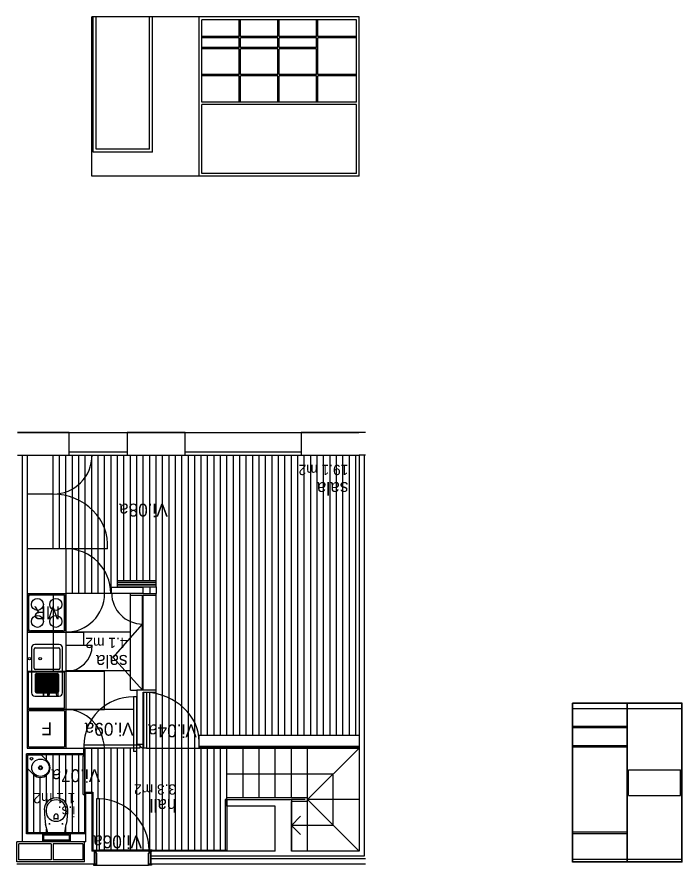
# Model space of a CAD drawing. Extents: x 1308.7 to 1320.6, y -286 to -262.2.
# Drawn here: x 1308.74 to 1319.07, y -275.33 to -262.16 of the extents above; entities that cross this region are included whole.
import ezdxf

# ---------------------------------------------------------------- set-up
doc = ezdxf.new("R2010")
doc.units = 0
for name, color, linetype in [('Level 1', 7, 'Continuous'), ('Level 10', 7, 'Continuous'), ('Level 11', 7, 'Continuous'), ('Level 12', 7, 'Continuous'), ('Level 13', 7, 'Continuous'), ('Level 2', 7, 'Continuous'), ('Level 21', 7, 'Continuous'), ('Level 3', 7, 'Continuous'), ('Level 31', 7, 'Continuous'), ('Level 36', 7, 'Continuous'), ('Level 4', 7, 'Continuous'), ('Level 60', 7, 'Continuous')]:
    doc.layers.add(name, color=color, linetype=linetype)

msp = doc.modelspace()

# ---------------------------------------------------------------- linework, layer by layer
at = {"layer": 'Level 1'}
for p, q in [((1309.903, -264.629), (1309.903, -262.159)), ((1314.053, -262.159), (1309.903, -262.159)), ((1314.053, -264.629), (1314.053, -262.159)), ((1314.053, -264.629), (1309.903, -264.629)), ((1309.553, -268.612), (1308.753, -268.612)), ((1309.553, -268.962), (1309.553, -268.612)), ((1311.353, -268.612), (1310.453, -268.612)), ((1310.453, -268.612), (1310.453, -268.962)), ((1311.353, -268.962), (1311.353, -268.612)), ((1314.153, -268.612), (1313.153, -268.612)), ((1313.153, -268.612), (1313.153, -268.962)), ((1308.753, -268.962), (1308.853, -268.962)), ((1308.753, -268.962), (1309.553, -268.962)), ((1308.823, -268.962), (1308.823, -274.967)), ((1308.903, -268.962), (1308.903, -273.512)), ((1308.903, -268.962), (1308.903, -270.712)), ((1310.453, -268.962), (1311.353, -268.962)), ((1313.153, -268.962), (1314.053, -268.962)), ((1314.153, -268.962), (1314.053, -268.962)), ((1314.053, -268.962), (1314.053, -275.112)), ((1314.133, -268.962), (1314.133, -275.192)), ((1308.903, -270.812), (1308.903, -273.512)), ((1310.203, -271.012), (1310.703, -271.012)), ((1310.203, -271.012), (1310.203, -271.112)), ((1310.703, -271.112), (1310.203, -271.112)), ((1310.503, -271.144), (1310.503, -271.112)), ((1310.703, -271.112), (1310.703, -271.012)), ((1310.703, -271.112), (1310.903, -271.112)), ((1310.903, -271.144), (1310.903, -271.112)), ((1310.903, -271.144), (1310.503, -271.144)), ((1310.903, -272.612), (1310.603, -272.612)), ((1310.603, -272.612), (1310.603, -273.452)), ((1310.703, -272.612), (1310.603, -272.612)), ((1310.603, -272.612), (1310.603, -273.452)), ((1310.703, -273.452), (1310.703, -272.644)), ((1310.703, -272.644), (1310.903, -272.644)), ((1310.903, -272.644), (1310.903, -272.612)), ((1317.367, -275.285), (1317.367, -272.815)), ((1319.067, -272.815), (1317.367, -272.815)), ((1319.067, -275.285), (1319.067, -272.815)), ((1310.603, -273.452), (1310.703, -273.452)), ((1310.603, -273.452), (1310.703, -273.452)), ((1309.778, -273.602), (1308.893, -273.602)), ((1308.893, -274.842), (1308.893, -273.602)), ((1308.903, -273.512), (1309.778, -273.512)), ((1308.903, -273.512), (1309.778, -273.512)), ((1309.778, -273.617), (1308.908, -273.617)), ((1308.908, -273.617), (1308.908, -274.827)), ((1309.778, -273.512), (1309.778, -273.617)), ((1309.798, -274.212), (1309.903, -274.212)), ((1309.798, -274.827), (1309.798, -274.212)), ((1309.813, -274.967), (1309.813, -274.212)), ((1309.903, -274.212), (1309.903, -275.112)), ((1312.003, -274.412), (1312.003, -274.312)), ((1312.003, -274.312), (1313.003, -274.312)), ((1312.753, -274.412), (1312.003, -274.412)), ((1312.753, -275.112), (1312.753, -274.412)), ((1313.003, -274.312), (1313.003, -275.112)), ((1309.813, -274.842), (1308.893, -274.842)), ((1309.798, -274.827), (1308.908, -274.827)), ((1309.813, -274.967), (1308.743, -274.967)), ((1308.743, -275.277), (1308.743, -274.967)), ((1308.773, -275.247), (1308.773, -274.997)), ((1309.273, -274.997), (1308.773, -274.997)), ((1309.273, -274.997), (1309.273, -275.247)), ((1309.303, -274.997), (1309.303, -275.247)), ((1309.763, -274.997), (1309.303, -274.997)), ((1309.763, -274.997), (1309.763, -275.247)), ((1309.793, -275.277), (1309.793, -274.967)), ((1309.943, -275.112), (1309.903, -275.112)), ((1309.943, -275.112), (1309.943, -275.312)), ((1310.823, -275.112), (1310.823, -275.312)), ((1312.753, -275.112), (1310.823, -275.112)), ((1314.133, -275.192), (1310.823, -275.192)), ((1314.053, -275.112), (1313.003, -275.112)), ((1309.793, -275.277), (1308.743, -275.277)), ((1309.943, -275.312), (1308.743, -275.312)), ((1309.273, -275.247), (1308.773, -275.247)), ((1309.763, -275.247), (1309.303, -275.247)), ((1314.153, -275.232), (1310.823, -275.232)), ((1314.153, -275.312), (1310.823, -275.312)), ((1319.067, -275.285), (1317.367, -275.285))]:
    msp.add_line(p, q, dxfattribs=at)
at = {"layer": 'Level 10'}
for p, q in [((1309.403, -270.415), (1309.403, -268.962)), ((1309.503, -270.415), (1309.503, -268.962)), ((1309.603, -271.112), (1309.603, -268.962)), ((1309.703, -271.112), (1309.703, -268.962)), ((1309.803, -271.112), (1309.803, -268.962)), ((1309.903, -271.112), (1309.903, -268.962)), ((1310.003, -271.112), (1310.003, -268.962)), ((1310.103, -271.112), (1310.103, -268.962)), ((1310.203, -271.007), (1310.203, -268.962)), ((1310.303, -270.907), (1310.303, -268.962)), ((1310.403, -270.907), (1310.403, -268.962)), ((1310.503, -270.907), (1310.503, -268.962)), ((1310.603, -270.907), (1310.603, -268.962)), ((1310.703, -270.907), (1310.703, -268.962)), ((1310.803, -270.907), (1310.803, -268.962)), ((1310.903, -270.907), (1310.903, -268.962)), ((1311.003, -275.097), (1311.003, -268.962)), ((1311.103, -275.097), (1311.103, -268.962)), ((1311.203, -275.097), (1311.203, -268.962)), ((1311.303, -275.097), (1311.303, -268.962)), ((1311.403, -275.097), (1311.403, -268.962)), ((1311.503, -275.097), (1311.503, -268.962)), ((1311.603, -273.312), (1311.603, -268.962)), ((1311.703, -273.312), (1311.703, -268.962)), ((1311.803, -273.312), (1311.803, -268.962)), ((1311.903, -273.312), (1311.903, -268.962)), ((1312.003, -273.312), (1312.003, -268.962)), ((1312.103, -273.312), (1312.103, -268.962)), ((1312.203, -273.312), (1312.203, -268.962)), ((1312.303, -273.312), (1312.303, -268.962)), ((1312.403, -273.312), (1312.403, -268.962)), ((1312.503, -273.312), (1312.503, -268.962)), ((1312.603, -273.312), (1312.603, -268.962)), ((1312.703, -273.312), (1312.703, -268.962)), ((1312.803, -273.312), (1312.803, -268.962)), ((1312.903, -273.312), (1312.903, -268.962)), ((1313.003, -273.312), (1313.003, -268.962)), ((1313.103, -273.312), (1313.103, -268.962)), ((1313.203, -273.312), (1313.203, -268.962)), ((1313.303, -273.312), (1313.303, -268.962)), ((1313.403, -273.312), (1313.403, -268.962)), ((1313.503, -273.312), (1313.503, -268.962)), ((1313.603, -273.312), (1313.603, -268.962)), ((1313.703, -273.312), (1313.703, -268.962)), ((1313.803, -273.312), (1313.803, -268.962)), ((1313.903, -273.312), (1313.903, -268.962)), ((1314.003, -273.312), (1314.003, -268.962)), ((1310.203, -271.112), (1309.506, -271.112)), ((1310.803, -271.007), (1310.803, -271.112)), ((1310.903, -271.007), (1310.903, -271.112)), ((1310.503, -271.712), (1309.503, -271.712)), ((1310.503, -272.312), (1309.503, -272.312)), ((1310.803, -275.097), (1310.803, -272.644)), ((1310.903, -275.097), (1310.903, -272.644)), ((1310.553, -272.912), (1309.503, -272.912)), ((1310.603, -275.112), (1310.603, -273.452)), ((1310.703, -275.112), (1310.703, -273.452)), ((1309.203, -273.699), (1309.203, -273.617)), ((1309.303, -274.293), (1309.303, -273.617)), ((1309.403, -274.294), (1309.403, -273.617)), ((1309.503, -274.37), (1309.503, -273.617)), ((1309.603, -274.827), (1309.603, -273.617)), ((1309.703, -274.827), (1309.703, -273.617)), ((1309.803, -274.197), (1309.803, -273.512)), ((1309.903, -274.197), (1309.903, -273.512)), ((1310.003, -274.297), (1310.003, -273.512)), ((1310.103, -275.112), (1310.103, -273.512)), ((1310.203, -275.112), (1310.203, -273.512)), ((1310.303, -275.112), (1310.303, -273.512)), ((1310.403, -275.112), (1310.403, -273.512)), ((1310.503, -275.112), (1310.503, -273.512)), ((1311.603, -275.097), (1311.603, -273.512)), ((1311.703, -275.097), (1311.703, -273.512)), ((1311.803, -275.097), (1311.803, -273.512)), ((1311.903, -275.097), (1311.903, -273.512)), ((1309.003, -274.827), (1309.003, -273.925)), ((1309.103, -274.827), (1309.103, -273.967)), ((1309.203, -274.358), (1309.203, -273.935)), ((1309.203, -274.827), (1309.203, -274.77)), ((1309.503, -274.827), (1309.503, -274.727)), ((1310.793, -275.112), (1309.973, -275.112))]:
    msp.add_line(p, q, dxfattribs=at)
at = {"layer": 'Level 11'}
for p, q in [((1309.453, -271.132), (1308.953, -271.132)), ((1308.923, -271.662), (1308.923, -271.162)), ((1309.483, -271.662), (1309.483, -271.162)), ((1309.453, -271.692), (1308.953, -271.692)), ((1309.008, -272.273), (1309.008, -271.973)), ((1309.028, -271.953), (1309.388, -271.953)), ((1309.408, -271.973), (1309.408, -272.273)), ((1309.388, -272.293), (1309.028, -272.293)), ((1309.028, -272.371), (1309.028, -272.633)), ((1309.048, -272.351), (1309.368, -272.351)), ((1309.048, -272.351), (1309.048, -272.653)), ((1309.068, -272.351), (1309.068, -272.653)), ((1309.088, -272.351), (1309.088, -272.653)), ((1309.108, -272.351), (1309.108, -272.653)), ((1309.128, -272.351), (1309.128, -272.653)), ((1309.148, -272.351), (1309.148, -272.653)), ((1309.168, -272.351), (1309.168, -272.653)), ((1309.188, -272.351), (1309.188, -272.653)), ((1309.208, -272.351), (1309.208, -272.653)), ((1309.228, -272.351), (1309.228, -272.653)), ((1309.248, -272.351), (1309.248, -272.653)), ((1309.268, -272.351), (1309.268, -272.653)), ((1309.288, -272.351), (1309.288, -272.653)), ((1309.308, -272.351), (1309.308, -272.653)), ((1309.328, -272.351), (1309.328, -272.653)), ((1309.348, -272.351), (1309.348, -272.653)), ((1309.368, -272.351), (1309.368, -272.653)), ((1309.388, -272.371), (1309.388, -272.633)), ((1309.048, -272.653), (1309.368, -272.653)), ((1309.483, -272.932), (1308.923, -272.932)), ((1308.923, -273.492), (1308.923, -272.932)), ((1309.483, -272.932), (1309.483, -273.492)), ((1308.923, -273.492), (1309.483, -273.492)), ((1308.908, -273.617), (1309.12, -273.617)), ((1308.908, -273.829), (1308.908, -273.617)), ((1309.214, -273.711), (1309.12, -273.617)), ((1309.002, -273.923), (1308.908, -273.829)), ((1309.168, -274.468), (1309.168, -274.464)), ((1309.198, -274.464), (1309.198, -274.5)), ((1309.503, -274.464), (1309.503, -274.5)), ((1309.533, -274.468), (1309.533, -274.464)), ((1309.24, -274.688), (1309.26, -274.688)), ((1309.25, -274.698), (1309.25, -274.678)), ((1309.32, -274.622), (1309.32, -274.565)), ((1309.32, -274.604), (1309.38, -274.604)), ((1309.38, -274.622), (1309.38, -274.565)), ((1309.44, -274.688), (1309.46, -274.688)), ((1309.45, -274.698), (1309.45, -274.678)), ((1309.221, -274.827), (1309.187, -274.695)), ((1309.485, -274.827), (1309.509, -274.695)), ((1309.138, -274.847), (1309.138, -274.957)), ((1309.568, -274.847), (1309.138, -274.847)), ((1309.553, -274.862), (1309.153, -274.862)), ((1309.153, -274.862), (1309.153, -274.942)), ((1309.553, -274.942), (1309.153, -274.942)), ((1309.221, -274.827), (1309.485, -274.827)), ((1309.553, -274.862), (1309.553, -274.942)), ((1309.568, -274.847), (1309.568, -274.957)), ((1309.568, -274.957), (1309.138, -274.957))]:
    msp.add_line(p, q, dxfattribs=at)
for points in [[(1309.399, -271.902), (1309.02, -271.902)], [(1308.97, -271.952), (1308.97, -272.653)], [(1309.449, -272.653), (1309.449, -271.952)], [(1309.02, -272.703), (1309.399, -272.703)]]:
    msp.add_lwpolyline(points, dxfattribs=at)
for centre, radius in [((1309.06, -271.28), 0.0936), ((1309.346, -271.28), 0.0936), ((1309.06, -271.544), 0.0936), ((1309.346, -271.544), 0.0936), ((1308.938, -272.123), 0.0199), ((1309.104, -272.123), 0.0199), ((1308.968, -273.677), 0.02), ((1309.108, -273.817), 0.135), ((1309.108, -273.817), 0.03), ((1309.108, -273.817), 0.02)]:
    msp.add_circle(centre, radius, dxfattribs=at)
for centre, radius, start, end in [((1308.953, -271.162), 0.03, 90, 179.9998), ((1309.453, -271.162), 0.03, 360, 89.9999), ((1308.953, -271.662), 0.03, 179.9998, 270.0001), ((1309.453, -271.662), 0.03, 269.9999, 359.9999), ((1309.02, -271.952), 0.05, 90, 180), ((1309.399, -271.952), 0.05, 0, 90), ((1309.028, -271.973), 0.02, 90, 180), ((1309.388, -271.973), 0.02, 0, 90), ((1309.028, -272.273), 0.02, 180, 270), ((1309.388, -272.273), 0.02, 270, 0), ((1309.048, -272.371), 0.02, 90, 180), ((1309.368, -272.371), 0.02, 0, 90), ((1309.02, -272.653), 0.05, 180, 270), ((1309.048, -272.633), 0.02, 180, 270), ((1309.368, -272.633), 0.02, 270, 0), ((1309.399, -272.653), 0.05, 270, 0), ((1309.108, -273.817), 0.15, 225.0002, 45), ((1309.35, -274.565), 0.03, 359.9987, 180.0005)]:
    msp.add_arc(centre, radius, start, end, dxfattribs=at)
for centre, major_axis, ratio, start_param, end_param in [((1309.35, -274.464), (0.183, 0), 0.972581, 0.000002, 3.141589), ((1309.35, -274.464), (0.153, 0), 0.967187, 0.000002, 3.141589), ((1310.568, -274.468), (0, 1.4), 0.999692, 1.570794, 1.733712), ((1309.35, -274.5), (0.153, 0), 0.967187, 3.141595, 6.283182), ((1307.755, -274.468), (1.778, 0), 0.787256, 6.120268, 6.283186)]:
    msp.add_ellipse(centre, major_axis=major_axis, ratio=ratio, start_param=start_param, end_param=end_param, dxfattribs=at)
at = {"layer": 'Level 12'}
for p, q in [((1311.571, -264.629), (1311.571, -262.159)), ((1314.013, -262.204), (1311.611, -262.204)), ((1311.611, -263.48), (1311.611, -262.204)), ((1312.193, -262.464), (1312.193, -262.204)), ((1312.213, -262.464), (1312.213, -262.204)), ((1312.793, -262.464), (1312.793, -262.204)), ((1312.813, -262.464), (1312.813, -262.204)), ((1313.393, -262.464), (1313.393, -262.204)), ((1313.413, -262.464), (1313.413, -262.204)), ((1314.013, -263.48), (1314.013, -262.204)), ((1312.193, -262.464), (1311.611, -262.464)), ((1312.193, -262.484), (1311.611, -262.484)), ((1312.193, -262.634), (1312.193, -262.484)), ((1312.793, -262.464), (1312.213, -262.464)), ((1312.793, -262.484), (1312.213, -262.484)), ((1312.213, -262.634), (1312.213, -262.484)), ((1312.793, -262.634), (1312.793, -262.484)), ((1313.393, -262.464), (1312.813, -262.464)), ((1312.813, -262.634), (1312.813, -262.484)), ((1313.393, -262.484), (1312.813, -262.484)), ((1313.393, -262.634), (1313.393, -262.484)), ((1314.013, -262.464), (1313.413, -262.464)), ((1314.013, -262.484), (1313.413, -262.484)), ((1313.413, -263.055), (1313.413, -262.484)), ((1312.193, -262.634), (1311.611, -262.634)), ((1312.193, -262.654), (1311.611, -262.654)), ((1312.193, -263.055), (1312.193, -262.654)), ((1312.793, -262.634), (1312.213, -262.634)), ((1312.793, -262.654), (1312.213, -262.654)), ((1312.213, -263.055), (1312.213, -262.654)), ((1312.793, -263.055), (1312.793, -262.654)), ((1313.393, -262.634), (1312.813, -262.634)), ((1313.393, -262.654), (1312.813, -262.654)), ((1312.813, -263.055), (1312.813, -262.654)), ((1313.393, -263.055), (1313.393, -262.654)), ((1312.193, -263.055), (1311.611, -263.055)), ((1312.193, -263.075), (1311.611, -263.075)), ((1312.193, -263.48), (1312.193, -263.075)), ((1312.793, -263.055), (1312.213, -263.055)), ((1312.793, -263.075), (1312.213, -263.075)), ((1312.213, -263.48), (1312.213, -263.075)), ((1312.793, -263.48), (1312.793, -263.075)), ((1313.393, -263.055), (1312.813, -263.055)), ((1313.393, -263.075), (1312.813, -263.075)), ((1312.813, -263.48), (1312.813, -263.075)), ((1313.393, -263.48), (1313.393, -263.075)), ((1314.013, -263.055), (1313.413, -263.055)), ((1314.013, -263.075), (1313.413, -263.075)), ((1313.413, -263.48), (1313.413, -263.075)), ((1314.013, -263.48), (1311.611, -263.48)), ((1314.013, -263.52), (1311.611, -263.52)), ((1311.611, -264.589), (1311.611, -263.52)), ((1314.013, -264.589), (1314.013, -263.52)), ((1314.053, -264.629), (1311.571, -264.629)), ((1314.013, -264.589), (1311.611, -264.589))]:
    msp.add_line(p, q, dxfattribs=at)
at = {"layer": 'Level 13'}
for p, q in [((1309.928, -264.259), (1309.928, -262.159)), ((1309.973, -264.214), (1309.973, -262.159)), ((1310.8, -264.214), (1310.8, -262.159)), ((1310.845, -264.259), (1310.845, -262.159)), ((1310.845, -264.259), (1309.928, -264.259)), ((1310.8, -264.214), (1309.973, -264.214)), ((1309.303, -270.415), (1309.303, -268.962)), ((1309.503, -270.415), (1308.903, -270.415)), ((1309.503, -270.415), (1309.503, -273.512)), ((1310.303, -270.907), (1310.903, -270.907)), ((1310.303, -271.007), (1310.303, -270.907)), ((1310.303, -270.937), (1310.903, -270.937)), ((1310.303, -270.942), (1310.903, -270.942)), ((1310.303, -270.972), (1310.903, -270.972)), ((1310.303, -270.977), (1310.903, -270.977)), ((1310.903, -271.007), (1310.903, -270.907)), ((1310.903, -271.007), (1310.903, -270.907)), ((1310.303, -271.007), (1310.903, -271.007)), ((1310.708, -272.647), (1310.708, -273.512)), ((1310.753, -272.647), (1310.708, -272.647)), ((1310.753, -272.647), (1310.753, -273.512)), ((1310.598, -272.717), (1310.553, -272.717)), ((1310.553, -272.717), (1310.553, -273.562)), ((1310.598, -272.717), (1310.598, -273.562)), ((1319.062, -272.82), (1317.367, -272.82)), ((1317.372, -275.28), (1317.372, -272.815)), ((1318.216, -275.28), (1318.216, -272.82)), ((1318.218, -275.28), (1318.218, -272.82)), ((1319.062, -275.28), (1319.062, -272.82)), ((1309.503, -272.912), (1308.903, -272.912)), ((1311.571, -273.512), (1311.571, -273.312)), ((1311.571, -273.312), (1314.049, -273.312)), ((1309.768, -273.632), (1309.798, -273.632)), ((1309.768, -274.232), (1309.768, -273.632)), ((1309.778, -273.632), (1309.798, -273.632)), ((1309.798, -274.232), (1309.798, -273.632)), ((1310.598, -273.562), (1310.553, -273.562)), ((1310.753, -273.512), (1310.708, -273.512)), ((1311.571, -273.512), (1314.053, -273.512)), ((1311.571, -273.512), (1314.053, -273.512)), ((1311.571, -273.512), (1314.053, -273.512)), ((1311.999, -273.512), (1314.053, -273.512)), ((1318.238, -273.85), (1319.042, -273.85)), ((1318.238, -274.25), (1318.238, -273.85)), ((1319.042, -274.25), (1319.042, -273.85)), ((1309.768, -274.232), (1309.798, -274.232)), ((1309.798, -274.197), (1309.918, -274.197)), ((1309.918, -274.197), (1309.918, -275.112)), ((1318.238, -274.25), (1319.042, -274.25)), ((1309.978, -274.297), (1309.978, -275.097)), ((1310.022, -274.297), (1309.978, -274.297)), ((1310.022, -275.097), (1310.022, -274.297)), ((1311.973, -274.312), (1311.973, -275.097)), ((1312.003, -274.312), (1311.973, -274.312)), ((1312.003, -274.312), (1312.003, -275.112)), ((1309.923, -275.097), (1309.973, -275.097)), ((1309.923, -275.107), (1309.923, -275.097)), ((1309.928, -275.107), (1309.923, -275.107)), ((1309.928, -275.112), (1309.928, -275.107)), ((1309.973, -275.112), (1309.928, -275.112)), ((1309.953, -275.112), (1309.953, -275.312)), ((1309.973, -275.097), (1309.973, -275.112)), ((1309.973, -275.141), (1309.973, -275.112)), ((1309.983, -275.141), (1309.973, -275.141)), ((1309.978, -275.097), (1310.022, -275.097)), ((1309.983, -275.312), (1309.983, -275.141)), ((1310.783, -275.312), (1310.783, -275.141)), ((1310.783, -275.141), (1310.793, -275.141)), ((1310.843, -275.097), (1310.793, -275.097)), ((1310.793, -275.097), (1310.793, -275.112)), ((1310.793, -275.112), (1310.838, -275.112)), ((1310.793, -275.141), (1310.793, -275.112)), ((1310.793, -275.112), (1310.813, -275.112)), ((1310.813, -275.112), (1310.813, -275.312)), ((1310.838, -275.112), (1310.838, -275.107)), ((1310.838, -275.107), (1310.843, -275.107)), ((1310.843, -275.107), (1310.843, -275.097)), ((1310.843, -275.097), (1312.003, -275.097)), ((1309.938, -275.317), (1309.933, -275.317)), ((1309.933, -275.317), (1309.933, -275.327)), ((1309.933, -275.327), (1309.983, -275.327)), ((1309.983, -275.312), (1309.938, -275.312)), ((1309.938, -275.312), (1309.938, -275.317)), ((1309.953, -275.312), (1309.983, -275.312)), ((1309.983, -275.327), (1309.983, -275.312)), ((1310.813, -275.312), (1310.783, -275.312)), ((1310.783, -275.327), (1310.783, -275.312)), ((1310.783, -275.312), (1310.828, -275.312)), ((1310.833, -275.327), (1310.783, -275.327)), ((1310.828, -275.312), (1310.828, -275.317)), ((1310.828, -275.317), (1310.833, -275.317)), ((1310.833, -275.317), (1310.833, -275.327)), ((1318.216, -275.28), (1317.372, -275.28)), ((1319.062, -275.28), (1318.218, -275.28))]:
    msp.add_line(p, q, dxfattribs=at)
at = {"layer": 'Level 2'}
for p, q in [((1309.553, -268.612), (1310.453, -268.612)), ((1311.353, -268.612), (1313.153, -268.612)), ((1309.553, -268.912), (1310.453, -268.912)), ((1309.553, -268.962), (1310.453, -268.962)), ((1311.353, -268.912), (1313.153, -268.912)), ((1311.353, -268.962), (1313.153, -268.962)), ((1310.503, -272.612), (1310.503, -271.144)), ((1310.903, -272.612), (1310.903, -271.144)), ((1310.503, -272.612), (1310.603, -272.612)), ((1312.003, -274.312), (1312.003, -273.512)), ((1312.253, -274.282), (1312.253, -273.512)), ((1312.503, -274.282), (1312.503, -273.512)), ((1312.753, -274.282), (1312.753, -273.512)), ((1313.003, -274.282), (1313.003, -273.512)), ((1313.253, -274.282), (1313.253, -273.512)), ((1313.253, -274.312), (1314.053, -273.512)), ((1312.003, -273.912), (1313.653, -273.912)), ((1313.653, -274.712), (1313.653, -273.912)), ((1313.253, -274.282), (1312.003, -274.282)), ((1313.253, -274.342), (1313.253, -274.282)), ((1313.219, -274.312), (1313.003, -274.312)), ((1313.003, -275.112), (1313.003, -274.342)), ((1313.253, -274.342), (1313.003, -274.342)), ((1314.053, -274.312), (1313.253, -274.312)), ((1313.253, -274.312), (1314.053, -275.112)), ((1313.253, -275.112), (1313.253, -274.342)), ((1313.144, -274.571), (1313.003, -274.712)), ((1313.144, -274.854), (1313.003, -274.712)), ((1313.653, -274.712), (1313.003, -274.712))]:
    msp.add_line(p, q, dxfattribs=at)
at = {"layer": 'Level 21'}
msp.add_line((1308.753, -268.612), (1314.048, -268.612), dxfattribs=at)
at = {"layer": 'Level 3'}
for p, q in [((1309.303, -271.112), (1309.303, -272.322)), ((1309.303, -271.112), (1309.503, -271.112)), ((1309.503, -272.322), (1308.903, -272.322))]:
    msp.add_line(p, q, dxfattribs=at)
at = {"layer": 'Level 31'}
for p, q in [((1309.798, -273.512), (1309.778, -273.512)), ((1309.798, -273.617), (1309.778, -273.617)), ((1309.798, -273.512), (1309.798, -273.617))]:
    msp.add_line(p, q, dxfattribs=at)
at = {"layer": 'Level 36'}
for p, q in [((1310.693, -272.612), (1310.693, -271.144)), ((1310.703, -272.612), (1310.703, -271.144)), ((1311.571, -273.482), (1314.053, -273.482)), ((1311.571, -273.492), (1314.053, -273.492))]:
    msp.add_line(p, q, dxfattribs=at)
at = {"layer": 'Level 4'}
for p, q in [((1309.303, -269.568), (1308.903, -269.568)), ((1310.148, -270.415), (1309.303, -270.415)), ((1308.903, -271.112), (1309.303, -271.112)), ((1308.923, -271.132), (1309.483, -271.132)), ((1308.923, -271.132), (1308.923, -271.692)), ((1309.483, -271.132), (1309.483, -271.692)), ((1310.237, -272.105), (1310.693, -271.587)), ((1308.903, -271.712), (1309.503, -271.71)), ((1308.923, -271.692), (1309.483, -271.692)), ((1309.503, -271.71), (1309.78, -271.71)), ((1309.78, -271.914), (1309.78, -271.71)), ((1309.503, -271.914), (1309.911, -271.914)), ((1310.693, -272.612), (1310.237, -272.105)), ((1309.483, -272.332), (1308.923, -272.332)), ((1308.923, -272.892), (1308.923, -272.332)), ((1309.483, -272.892), (1309.483, -272.332)), ((1310.103, -272.322), (1309.503, -272.322)), ((1310.103, -272.912), (1310.103, -272.322)), ((1308.923, -272.892), (1309.483, -272.892)), ((1309.503, -272.912), (1310.103, -272.912)), ((1319.062, -272.9), (1317.367, -272.9)), ((1318.218, -273.178), (1317.372, -273.178)), ((1318.218, -273.198), (1317.372, -273.198)), ((1310.648, -273.467), (1309.783, -273.467)), ((1309.783, -273.477), (1309.783, -273.512)), ((1310.648, -273.467), (1310.648, -273.512)), ((1318.218, -273.475), (1317.367, -273.475)), ((1318.218, -273.495), (1317.367, -273.495)), ((1308.903, -273.512), (1309.503, -273.512)), ((1309.503, -273.512), (1310.103, -273.512)), ((1310.648, -273.512), (1309.783, -273.512)), ((1310.753, -273.512), (1311.571, -273.512)), ((1318.216, -274.815), (1317.367, -274.815)), ((1318.216, -274.845), (1317.367, -274.845)), ((1310.793, -275.097), (1310.022, -275.097)), ((1309.983, -275.327), (1310.783, -275.327)), ((1319.067, -275.24), (1317.372, -275.24))]:
    msp.add_line(p, q, dxfattribs=at)
for centre, radius, start, end in [((1309.303, -268.962), 0.606, 270, 0), ((1309.503, -271.112), 0.697, 0, 90), ((1309.503, -271.11), 0.6, 270, 359.7775), ((1310.693, -271.105), 0.48, 180, 270), ((1309.503, -271.914), 0.408, 270, 0), ((1310.537, -273.471), 0.754, 88.8015, 180.4703), ((1310.708, -273.452), 0.06, 179.997, 270.0014)]:
    msp.add_arc(centre, radius, start, end, dxfattribs=at)
for centre, major_axis, ratio, start_param, end_param in [((1309.303, -270.359), (-0.847, 0), 0.932777, 3.069792, 4.712389), ((1310.688, -273.412), (-0.883, 0), 0.869294, 3.141609, 4.638298), ((1309.503, -273.563), (0, 0.651), 0.924693, 4.790593, 6.283185), ((1309.987, -275.097), (-0.806, 0), 0.992512, 3.141593, 4.668897)]:
    msp.add_ellipse(centre, major_axis=major_axis, ratio=ratio, start_param=start_param, end_param=end_param, dxfattribs=at)

# ---------------------------------------------------------------- texts
at = {"layer": 'Level 11'}
for s, p in [('MR', (1309.414, -271.312)), ('ML', (1309.412, -272.512)), ('F', (1309.287, -273.112))]:
    msp.add_text(s, height=0.2, rotation=180, dxfattribs=at).set_placement(p)
at = {"layer": 'Level 60'}
for s, height, p in [('19.1 m2', 0.16, (1313.887, -269.113)), ('sala', 0.2, (1313.887, -269.381)), ('Vi.08a', 0.2, (1311.085, -269.716)), ('4.1 m2', 0.16, (1310.459, -271.798)), ('sala', 0.2, (1310.459, -272.066)), ('Vi.09a', 0.2, (1310.553, -273.119)), ('Vi.04a', 0.2, (1311.535, -273.144)), ('Vi.07a', 0.2, (1310.036, -273.84)), ('3.3 m2', 0.16, (1311.214, -274.074)), ('1.1 m2', 0.16, (1309.65, -274.208)), ('i.s.', 0.16, (1309.65, -274.417)), ('hall', 0.2, (1311.219, -274.303)), ('Vi.06a', 0.2, (1310.683, -274.867))]:
    msp.add_text(s, height=height, rotation=180, dxfattribs=at).set_placement(p)

doc.saveas('drawing.dxf')
